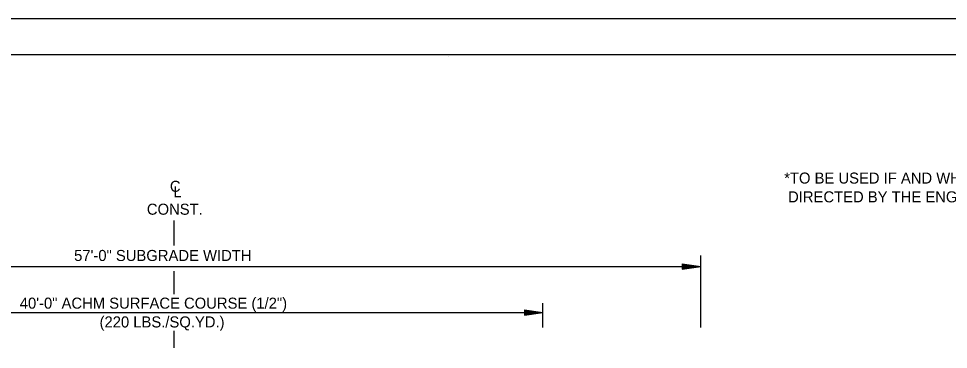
# Model space of a CAD drawing. Extents: x 1371763 to 1372860, y 385599 to 385872.
# Drawn here: x 1372352.1 to 1372402.6, y 385687.3 to 385705.3 of the extents above; entities that cross this region are included whole.
import ezdxf

# ---------------------------------------------------------------- set-up
doc = ezdxf.new("R2010")
doc.units = 0
for name, color, linetype in [('R_Border', 7, 'Continuous'), ('R_Draft', 7, 'Continuous'), ('R_No Plot', 7, 'Continuous')]:
    doc.layers.add(name, color=color, linetype=linetype)

msp = doc.modelspace()

# ---------------------------------------------------------------- linework, layer by layer
at = {"layer": 'R_Border'}
for p, q in [((1372299.208, 385703.307), (1372457.298, 385703.307)), ((1372375.468, 385703.177), (1372375.468, 385703.177)), ((1372375.468, 385703.177), (1372375.468, 385703.177))]:
    msp.add_line(p, q, dxfattribs=at)
at = {"layer": 'R_Draft'}
for p, q in [((1372360.579, 385692.935), (1372360.579, 385694.285)), ((1372389.145, 385688.475), (1372389.145, 385692.385)), ((1372388.145, 385691.935), (1372389.145, 385691.785)), ((1372388.145, 385691.935), (1372388.145, 385691.635)), ((1372388.145, 385691.91), (1372388.978, 385691.785)), ((1372388.145, 385691.885), (1372388.806, 385691.785)), ((1372388.145, 385691.86), (1372388.64, 385691.785)), ((1372388.145, 385691.834), (1372388.47, 385691.785)), ((1372332.008, 385691.785), (1372389.145, 385691.785)), ((1372360.579, 385690.285), (1372360.579, 385691.535)), ((1372388.145, 385691.809), (1372388.303, 385691.785)), ((1372388.145, 385691.635), (1372389.145, 385691.785)), ((1372388.145, 385691.736), (1372388.47, 385691.785)), ((1372388.145, 385691.686), (1372388.806, 385691.785)), ((1372388.145, 385691.66), (1372388.978, 385691.785)), ((1372388.145, 385691.711), (1372388.64, 385691.785)), ((1372388.145, 385691.762), (1372388.303, 385691.785)), ((1372379.578, 385689.435), (1372380.578, 385689.285)), ((1372379.578, 385689.435), (1372379.578, 385689.135)), ((1372379.578, 385689.41), (1372380.411, 385689.285)), ((1372379.578, 385689.385), (1372380.239, 385689.285)), ((1372379.578, 385689.36), (1372380.073, 385689.285)), ((1372379.578, 385689.334), (1372379.903, 385689.285)), ((1372379.578, 385689.309), (1372379.736, 385689.285)), ((1372380.578, 385688.475), (1372380.578, 385689.795)), ((1372340.576, 385689.285), (1372380.578, 385689.285)), ((1372379.578, 385689.135), (1372380.578, 385689.285)), ((1372379.578, 385689.236), (1372379.903, 385689.285)), ((1372379.578, 385689.186), (1372380.239, 385689.285)), ((1372379.578, 385689.16), (1372380.411, 385689.285)), ((1372379.578, 385689.211), (1372380.073, 385689.285)), ((1372379.578, 385689.262), (1372379.736, 385689.285)), ((1372360.579, 385687.377), (1372360.579, 385688.285))]:
    msp.add_line(p, q, dxfattribs=at)
at = {"layer": 'R_No Plot'}
msp.add_line((1372293.007, 385705.254), (1372459.674, 385705.254), dxfattribs=at)
for points in [[(1372293.004, 385705.254), (1372459.674, 385705.254), (1372459.674, 385598.585), (1372293.004, 385598.585)], [(1372416.168, 385703.307), (1372425.978, 385703.307), (1372425.978, 385698.367), (1372434.034, 385698.367), (1372445.634, 385698.367), (1372445.634, 385682.032), (1372457.238, 385682.032), (1372457.298, 385600.577), (1372299.208, 385600.577), (1372299.208, 385703.307)]]:
    msp.add_lwpolyline(points, close=True, dxfattribs=at)

# ---------------------------------------------------------------- texts
at = {"layer": 'R_Draft'}
for s, p in [('*TO BE USED IF AND WHERE ', (1372393.671, 385696.29)), ('C', (1372360.354, 385695.842)), ('L', (1372360.541, 385695.542)), ('DIRECTED BY THE ENGINEER', (1372393.881, 385695.27)), ('CONST.', (1372359.106, 385694.598)), ('57\'-0" SUBGRADE WIDTH', (1372355.16, 385692.085)), ('40\'-0" ACHM SURFACE COURSE (1/2")', (1372352.212, 385689.495)), ('(220 LBS./SQ.YD.)', (1372356.54, 385688.475))]:
    msp.add_text(s, height=0.6, rotation=360, dxfattribs=at).set_placement(p)

doc.saveas('drawing.dxf')
